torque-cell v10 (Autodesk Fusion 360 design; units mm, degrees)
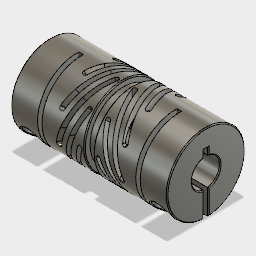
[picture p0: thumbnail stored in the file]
sketch "Sketch1"
  line L1 (-22.225, 11.1125) -> (22.225, 11.1125)
  line L2 (-22.225, -11.1125) -> (-22.225, 11.1125)
  line L3 (22.225, -11.1125) -> (-22.225, -11.1125)
  line L4 (22.225, 11.1125) -> (22.225, -11.1125)
  line L5 (-22.225, -11.1125) -> (22.225, 11.1125)
  line L6 (22.225, -11.1125) -> (-22.225, 11.1125)
  line L7 (-68, -4) -> (68, -4)
  line L8 (-68, 4) -> (-68, -4)
  line L9 (68, 4) -> (-68, 4)
  line L10 (68, -4) -> (68, 4)
  line L11 (-68, 4) -> (68, -4)
  line L12 (68, 4) -> (-68, -4)
  line L13 (0, 11.1125) -> (0, -11.1125)
  line L14 (22.225, 0) -> (-22.225, 0)
  line L15 (14.605, -11.1125) -> (13.335, -11.1125)
  line L16 (14.605, 12.3825) -> (14.605, -11.1125)
  line L17 (13.335, 12.3825) -> (14.605, 12.3825)
  line L18 (13.335, -11.1125) -> (13.335, 12.3825)
  circle C1 centre (18.415, -7.3025) radius 1.5
  circle C2 centre (18.415, -7.3025) radius 3
  circle C3 centre (-18.415, -7.3025) radius 3
  circle C4 centre (-18.415, -7.3025) radius 1.5
  point P12 (18.415, -7.3025)
  point P5 (22.225, -11.1125)
  point P4 (-22.225, -11.1125)
  point P2 (22.225, 11.1125)
  point P22 (14.605, 12.3825)
  point P23 (13.335, 12.3825)
  point P21 (14.605, -11.1125)
  dimension "d1" diameter C1 = 3
  dimension "d2" distance L4 P12 = 3.81
  dimension "d3" distance P5 P12 = 3.81
  dimension "d4" diameter C2 = 6
  dimension "d5" distance P4 P5 = 44.45
  dimension "d6" distance P2 P5 = 22.225
  dimension "d7" distance L7 L9 = 8
  dimension "d16" distance P22 P23 = 1.27
  dimension "d18" distance P5 P21 = 7.62
  dimension "d46" distance P2 P22 = 1.27
revolve "Revolve1" sketch "Sketch1" AlongAngle 360
extrude "Extrude1" cut sketch "Sketch1" profile of C1 C4 no distance stored
extrude "Extrude2" sketch "Sketch1" profile of C1 C2 C3 C4 no distance stored from offset 3.175
extrude "Extrude4" cut sketch "Sketch1" profile of L3 L7 L9 L14 L15 L16 L17 L18 no distance stored second side blind 0.635
sketch "Sketch2" plane through (22.225, 0, 0) normal (1, 0, 0) x axis (0, 0, -1)
  line L1 (0.635, 6.0325) -> (0.635, -11.0943)
  line L2 (0, -4) -> (0, 4)
  line L3 (-0.635, 6.0325) -> (-0.635, -11.0943)
  line L4 (-0.635, 6.0325) -> (0.635, 6.0325)
  circle C1 centre (0, 0) radius 11.1125
  circle C2 centre (0, 0) radius 4
  point P4 (0.635, 6.0325)
  point P9 (0, 11.1125)
  dimension "d12" distance L1 L3 = 1.27
  dimension "d13" distance P4 P9 = 5.08
extrude "Extrude3" cut sketch "Sketch2" against normal blind 7.62
mirror "Mirror1"
thread "Thread1"
work_plane "WorkPlane1" AlongDistance 1.778
sketch "Sketch3" plane through (1.778, 0, 0) normal (1, 0, 0) x axis (0, 0, -1)
  arc A1 centre (0, 0) radius 11.1125 clockwise from (-0.635, -11.0943) to (0.635, -11.0943)
  arc A2 centre (0, 0) radius 11.1125 clockwise from (-0.635, -11.0943) to (0.635, 11.0943)
  arc A3 centre (0, 0) radius 11.1125 clockwise from (0.635, -11.0943) to (0.635, 11.0943)
coil_primitive "CoilPrimitive1" Diameter 25.4 SectionSize 2.54 TaperAngle 0 Revolutions 0.3 Height 7.62
sketch "Sketch4" plane through (0, 0, 0) normal (0, 1, 0) x axis (1, 0, 0)
  line L1 (-22.225, 0.635) -> (-13.335, 0.635)
  line L2 (-22.225, 4) -> (-22.225, 0.635)
  line L3 (-13.335, 0.635) -> (-22.225, 0.635)
  line L4 (-13.335, -4) -> (-13.335, 0.635)
  line L5 (13.335, 0.635) -> (22.225, 0.635)
  line L6 (13.335, 0.635) -> (13.335, -4)
  line L7 (22.225, 0.635) -> (13.335, 0.635)
  line L8 (22.225, 4) -> (22.225, 0.635)
  line L9 (3.048, 12.7) -> (1.778, 12.7)
  line L10 (3.048, 0) -> (3.048, 12.7)
  line L11 (1.778, 0) -> (3.048, 0)
  line L12 (1.778, 12.7) -> (1.778, 0)
  line L13 (3.048, 12.7) -> (1.778, 12.7)
  line L14 (3.048, 15.24) -> (3.048, 12.7)
  line L15 (1.778, 15.24) -> (3.048, 15.24)
  line L16 (1.778, 12.7) -> (1.778, 15.24)
  line L17 (-1.27, 9.525) -> (1.27, 9.525)
  line L18 (-1.27, 12.065) -> (-1.27, 9.525)
  line L19 (1.27, 12.065) -> (-1.27, 12.065)
  line L20 (1.27, 9.525) -> (1.27, 12.065)
  line L21 (-1.27, 12.065) -> (1.27, 9.525)
  line L22 (1.27, 12.065) -> (-1.27, 9.525)
  line L23 (0, 10.795) -> (0, 0)
  line L24 (1.778, 0) -> (0, 0)
  line L25 (1.27, -12.065) -> (-1.27, -12.065)
  line L26 (-1.27, -9.525) -> (1.27, -9.525)
  line L27 (1.27, -9.525) -> (1.27, -12.065)
  line L28 (-1.27, -12.065) -> (-1.27, -9.525)
  point P10 (1.778, 12.7)
  point P11 (3.048, 12.7)
  point P16 (3.048, 12.7)
  point P17 (3.048, 15.24)
  point P21 (-1.27, 12.065)
  point P22 (1.27, 12.065)
  point P20 (-1.27, 9.525)
  dimension "d29" distance P10 P11 = 1.27
  dimension "d36" distance P16 P17 = 2.54
  dimension "d40" distance P21 P22 = 2.54
  dimension "d41" distance L17 L26 = 19.05
  dimension "d42" distance P20 P21 = 2.54
sweep "Sweep1" sketch "Sketch4" TwistAngle 0 TaperAngle 0
fillet "Fillet1" radius 0.635
circular_pattern "C-Pattern1" TotalAngle 360
mirror "Mirror2"
revolve "Revolve2" sketch "Sketch4" AlongAngle 360
chamfer "Chamfer1" distance 0.254
remove_body "RemoveBody1"
sketch "Sketch8" plane through (22.225, 0, 0) normal (1, 0, 0) x axis (0, 0, -1)
  line L1 (-0.889, 6.2865) -> (-0.889, 4.1601)
  line L2 (0.889, 6.2865) -> (-0.889, 6.2865)
  line L3 (0.889, 4.1601) -> (0.889, 6.2865)
  line L4 (0.889, -10.822) -> (0.889, -4.1601)
  line L5 (-0.889, -4.1601) -> (-0.889, -10.822)
  arc A1 centre (0, 0) radius 4.254 clockwise from (-0.889, -4.1601) to (-0.889, 4.1601)
  arc A2 centre (0, 0) radius 4.254 clockwise from (0.889, 4.1601) to (0.889, -4.1601)
  arc A3 centre (0, 0) radius 10.8585 clockwise from (-0.889, -10.822) to (0.889, -10.822)
  circle C1 centre (0, 0) radius 4
extrude "Extrude5" sketch "Sketch8" profile of C1 blind 12.7 second side blind 7.62
mirror "Mirror3"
